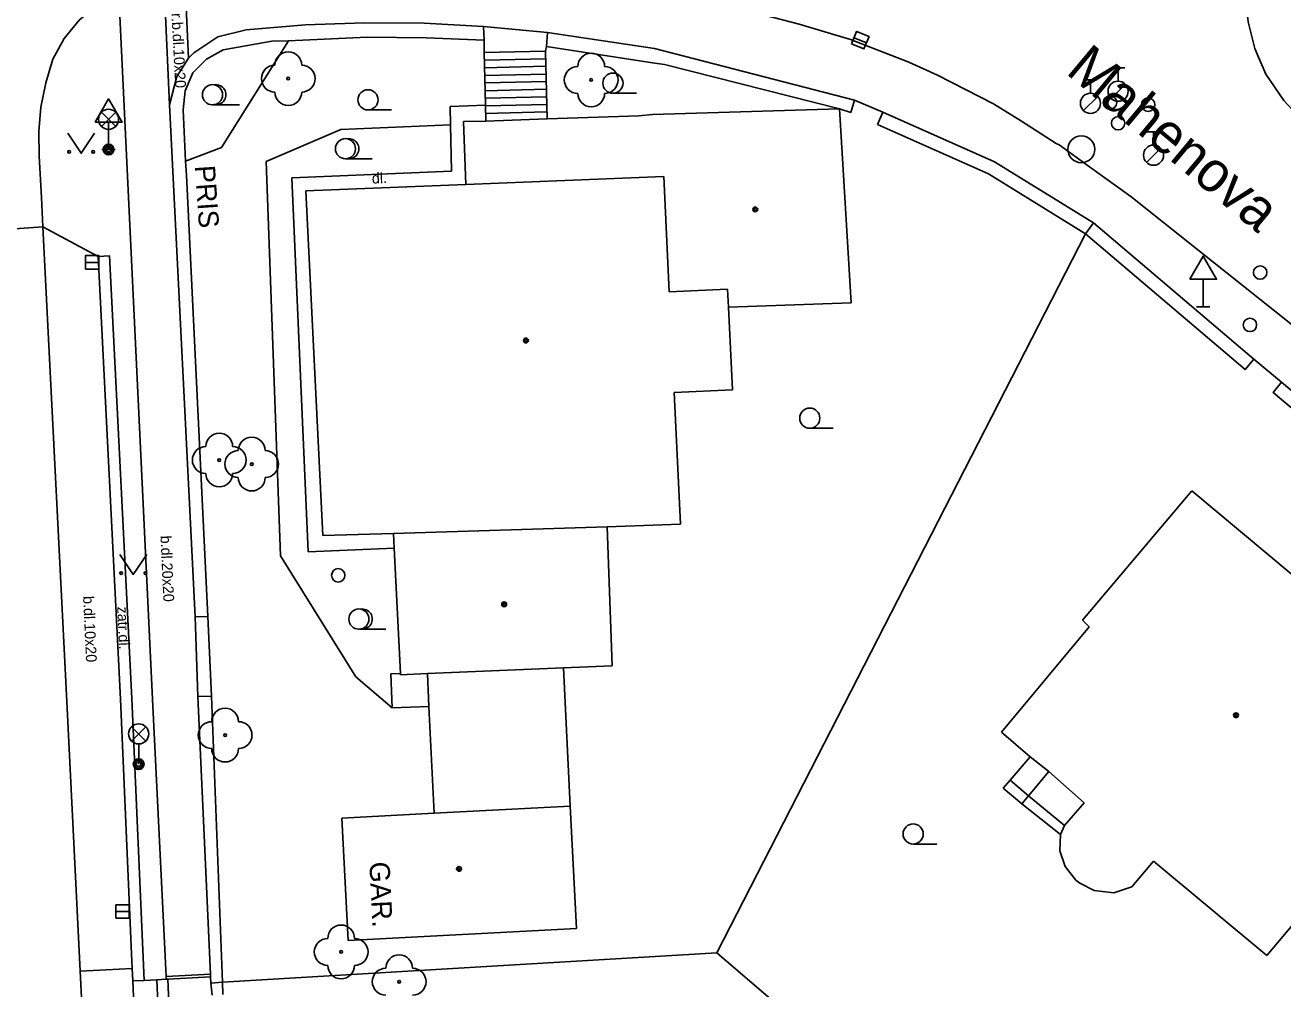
# Model space of a CAD drawing. Extents: x -600309 to -598967, y -1161267 to -1160292.
# Drawn here: x -599774.56 to -599727.72, y -1160467.69 to -1160431.81 of the extents above; entities that cross this region are included whole.
import ezdxf

# ---------------------------------------------------------------- set-up
doc = ezdxf.new("R2010")
doc.units = 0
for name, color, linetype in [('Level 10', 7, 'Continuous'), ('Level 11', 7, 'Continuous'), ('Level 21', 7, 'Continuous'), ('Level 22', 7, 'Continuous'), ('Level 27', 7, 'Continuous'), ('Level 28', 7, 'Continuous'), ('Level 33', 7, 'Continuous'), ('Level 34', 7, 'Continuous'), ('Level 36', 7, 'Continuous'), ('Level 39', 7, 'Continuous'), ('Level 40', 7, 'Continuous'), ('Level 41', 7, 'Continuous'), ('Level 5', 7, 'Continuous'), ('Level 50', 7, 'Continuous'), ('Level 51', 7, 'Continuous'), ('Level 7', 7, 'Continuous'), ('Level 8', 7, 'Continuous')]:
    doc.layers.add(name, color=color, linetype=linetype)

msp = doc.modelspace()

# ---------------------------------------------------------------- linework, layer by layer
at = {"layer": 'Level 10'}
for points in [[(-599725.57, -1160436.55), (-599726.98, -1160435.38), (-599727.23, -1160435.11), (-599727.69, -1160434.62), (-599728.36, -1160433.63), (-599728.67, -1160432.92), (-599728.67, -1160432.91), (-599728.77, -1160432.68), (-599729.02, -1160431.68), (-599729.04, -1160431.47), (-599729.12, -1160430.52), (-599729.02, -1160429.48), (-599728.93, -1160428.95), (-599727.47, -1160425.98), (-599727.28, -1160425.59)], [(-599773.52, -1160433.08), (-599773.1, -1160432.31), (-599772.54, -1160431.63), (-599771.87, -1160431.07), (-599771.1, -1160430.64)], [(-599750.81, -1160430.69), (-599747.65, -1160431.28), (-599745.73, -1160431.77), (-599743.83, -1160432.34), (-599741.65, -1160433.19), (-599740.59, -1160433.67), (-599738.5, -1160434.74)], [(-599774.03, -1160436.69), (-599774.05, -1160435.77), (-599773.97, -1160434.86), (-599773.79, -1160433.96), (-599773.52, -1160433.08)], [(-599738.5, -1160434.74), (-599737.46, -1160435.38), (-599736.16, -1160436.21), (-599736.06, -1160436.27), (-599734.93, -1160437.08), (-599733.39, -1160438.19)], [(-599773.9, -1160439.32), (-599773.95, -1160438.22), (-599774.03, -1160436.69)], [(-599733.39, -1160438.19), (-599726.76, -1160443.46)], [(-599773.9, -1160439.32), (-599771.84, -1160440.42)], [(-599771.84, -1160440.42), (-599771.01, -1160456.9), (-599770.6, -1160466.38), (-599770.57, -1160466.93)], [(-599770.57, -1160466.93), (-599770.55, -1160467.39), (-599770.4, -1160470.87), (-599770.38, -1160471.38)]]:
    msp.add_lwpolyline(points, dxfattribs=at)
at = {"layer": 'Level 11'}
for points in [[(-599771.1, -1160430.64), (-599771.04, -1160431.2), (-599769.82, -1160456.9)], [(-599769.18, -1160434.77), (-599769.34, -1160431.18), (-599768.56, -1160431.14), (-599768.47, -1160433.04)], [(-599757.4699, -1160432.37), (-599757.49, -1160431.86)], [(-599757.4699, -1160432.37), (-599757.46, -1160432.83)], [(-599755.15, -1160432.6), (-599755.11, -1160432.08)], [(-599757.46, -1160432.83), (-599755.18, -1160432.78)], [(-599757.46, -1160432.83), (-599757.41, -1160434.79), (-599757.4, -1160435.38)], [(-599755.18, -1160432.78), (-599755.15, -1160432.6)], [(-599755.18, -1160432.78), (-599755.12, -1160435.3)], [(-599757.45, -1160433.11), (-599755.17, -1160433.06)], [(-599757.45, -1160433.4), (-599755.17, -1160433.34)], [(-599757.44, -1160433.68), (-599755.1599, -1160433.63)], [(-599757.43, -1160433.96), (-599755.15, -1160433.9099)], [(-599757.43, -1160434.25), (-599755.15, -1160434.19)], [(-599758.73, -1160434.84), (-599757.41, -1160434.79)], [(-599757.42, -1160434.53), (-599755.14, -1160434.48)], [(-599757.4099, -1160434.81), (-599755.13, -1160434.76)], [(-599758.73, -1160434.84), (-599758.72, -1160435.52), (-599758.68, -1160437.24)], [(-599757.4099, -1160435.1), (-599755.13, -1160435.04)], [(-599764.63, -1160437.49), (-599758.68, -1160437.24)], [(-599764.63, -1160437.49), (-599764.02, -1160451.42)], [(-599773.9, -1160439.32), (-599776.88, -1160439.53), (-599779.91, -1160439.74)], [(-599772.51, -1160467.03), (-599773, -1160456.99), (-599773.9, -1160439.32)], [(-599771.84, -1160440.42), (-599771.41, -1160440.4), (-599770.58, -1160456.88), (-599770.13, -1160467.37)], [(-599760.81, -1160451.28), (-599764.02, -1160451.42)], [(-599754.26, -1160460.89), (-599754.51, -1160455.74)], [(-599760.58, -1160455.95), (-599760.94, -1160455.96)], [(-599760.89, -1160457.22), (-599760.94, -1160455.96)], [(-599759.58, -1160455.95), (-599759.52, -1160457.17), (-599759.33, -1160461.15)], [(-599769.82, -1160456.9), (-599769.31, -1160467.23), (-599769.31, -1160467.33)], [(-599759.52, -1160457.17), (-599760.89, -1160457.22)], [(-599737.88, -1160459.92), (-599737.14, -1160459.05)], [(-599736.44, -1160459.6), (-599737.19, -1160460.5)], [(-599738.14, -1160460.2199), (-599737.88, -1160459.92)], [(-599737.19, -1160460.5), (-599737.88, -1160459.92)], [(-599737.44, -1160460.8), (-599738.14, -1160460.2199)], [(-599737.19, -1160460.5), (-599737.44, -1160460.8)], [(-599735.86, -1160461.61), (-599737.19, -1160460.5)], [(-599736.01, -1160461.94), (-599737.44, -1160460.8)], [(-599772.51, -1160467.03), (-599770.57, -1160466.93)], [(-599772.29, -1160471.47), (-599772.51, -1160467.03)], [(-599769.31, -1160467.23), (-599767.66, -1160467.14)], [(-599770.13, -1160467.37), (-599770.55, -1160467.39)], [(-599769.31, -1160467.33), (-599769.65, -1160467.35), (-599770.13, -1160467.37)], [(-599769.65, -1160467.35), (-599769.5, -1160470.83)], [(-599769.31, -1160467.33), (-599769.25, -1160467.33), (-599767.65, -1160467.24)], [(-599769.25, -1160467.33), (-599769.1, -1160470.81)]]:
    msp.add_lwpolyline(points, dxfattribs=at)
at = {"layer": 'Level 21'}
for points in [[(-599767.25, -1160436.37), (-599764.75, -1160432.39)], [(-599762.8, -1160435.7), (-599765.58, -1160436.88)], [(-599762.8, -1160435.7), (-599758.72, -1160435.52)], [(-599767.25, -1160436.37), (-599768.58, -1160436.87)], [(-599765.58, -1160436.88), (-599765.05, -1160451.56)], [(-599765.05, -1160451.56), (-599762.24, -1160456.07)], [(-599762.24, -1160456.07), (-599760.89, -1160457.22)]]:
    msp.add_lwpolyline(points, dxfattribs=at)
at = {"layer": 'Level 22'}
for centre in [(-599764.76, -1160433.8), (-599753.48, -1160433.85), (-599767.33, -1160448), (-599766.12, -1160448.15), (-599767.11, -1160458.24), (-599762.79, -1160466.31), (-599760.63, -1160467.42)]:
    msp.add_circle(centre, 0.05, dxfattribs=at)
for centre, start, end in [((-599764.76, -1160433.3), 0, 180), ((-599753.48, -1160433.35), 0, 180), ((-599765.26, -1160433.8), 90, 270), ((-599764.26, -1160433.8), 270, 90), ((-599753.98, -1160433.85), 90, 270), ((-599752.98, -1160433.85), 270, 90), ((-599764.76, -1160434.3), 180, 0), ((-599753.48, -1160434.35), 180, 0), ((-599767.33, -1160447.5), 0, 180), ((-599766.12, -1160447.65), 0, 180), ((-599767.83, -1160448), 90, 270), ((-599766.62, -1160448.15), 90, 270), ((-599766.83, -1160448), 270, 90), ((-599765.62, -1160448.15), 270, 90), ((-599767.33, -1160448.5), 180, 0), ((-599766.12, -1160448.65), 180, 0), ((-599767.11, -1160457.74), 0, 180), ((-599767.61, -1160458.24), 90, 270), ((-599766.61, -1160458.24), 270, 90), ((-599767.11, -1160458.74), 180, 0), ((-599762.79, -1160465.81), 0, 180), ((-599763.29, -1160466.31), 90, 270), ((-599762.29, -1160466.31), 270, 90), ((-599760.63, -1160466.92), 0, 180), ((-599762.79, -1160466.81), 180, 0), ((-599761.13, -1160467.42), 90, 270), ((-599760.13, -1160467.42), 270, 90)]:
    msp.add_arc(centre, 0.5, start, end, dxfattribs=at)
at = {"layer": 'Level 27'}
for p, q in [((-599743.6915, -1160432.2756), (-599743.2285, -1160432.4644)), ((-599772.31, -1160440.64), (-599771.81, -1160440.64)), ((-599771.18, -1160464.81), (-599770.68, -1160464.81))]:
    msp.add_line(p, q, dxfattribs=at)
for points in [[(-599743.7859, -1160432.5071), (-599743.3229, -1160432.6959), (-599743.1341, -1160432.2329), (-599743.5971, -1160432.0441)], [(-599772.31, -1160440.89), (-599771.81, -1160440.89), (-599771.81, -1160440.39), (-599772.31, -1160440.39)], [(-599771.18, -1160465.06), (-599770.68, -1160465.06), (-599770.68, -1160464.56), (-599771.18, -1160464.56)]]:
    msp.add_lwpolyline(points, close=True, dxfattribs=at)
msp.add_circle((-599735.23, -1160436.43), 0.5, dxfattribs=at)
at = {"layer": 'Level 28'}
for p, q in [((-599734.11, -1160433.395), (-599733.61, -1160433.395)), ((-599733.86, -1160433.895), (-599733.86, -1160433.395)), ((-599735.14, -1160433.8449), (-599734.64, -1160433.8449)), ((-599734.89, -1160434.3449), (-599734.89, -1160433.8449)), ((-599734.118, -1160434.542), (-599733.588, -1160434.012)), ((-599735.148, -1160434.9919), (-599734.618, -1160434.4619)), ((-599732.79, -1160435.775), (-599732.29, -1160435.775)), ((-599732.54, -1160436.275), (-599732.54, -1160435.775)), ((-599732.798, -1160436.922), (-599732.268, -1160436.392))]:
    msp.add_line(p, q, dxfattribs=at)
for centre, radius in [((-599733.86, -1160434.27), 0.375), ((-599734.89, -1160434.7199), 0.375), ((-599734.1599, -1160434.69), 0.25), ((-599732.74, -1160434.77), 0.25), ((-599733.86, -1160435.46), 0.25), ((-599732.54, -1160436.65), 0.375), ((-599728.57, -1160441.02), 0.25), ((-599728.95, -1160442.9699), 0.25), ((-599762.9, -1160452.29), 0.25)]:
    msp.add_circle(centre, radius, dxfattribs=at)
at = {"layer": 'Level 33'}
for p, q in [((-599771.715, -1160435.58), (-599771.185, -1160435.05)), ((-599771.715, -1160435.05), (-599771.185, -1160435.58)), ((-599771.45, -1160435.69), (-599771.45, -1160436.44)), ((-599770.595, -1160458.46), (-599770.065, -1160457.93)), ((-599770.595, -1160457.93), (-599770.065, -1160458.46)), ((-599770.33, -1160458.57), (-599770.33, -1160459.32))]:
    msp.add_line(p, q, dxfattribs=at)
for centre, radius in [((-599771.45, -1160435.315), 0.375), ((-599771.45, -1160436.44), 0.2), ((-599771.45, -1160436.44), 0.1445), ((-599771.45, -1160436.44), 0.0876), ((-599770.33, -1160458.195), 0.375), ((-599770.33, -1160459.32), 0.2), ((-599770.33, -1160459.32), 0.1445), ((-599770.33, -1160459.32), 0.0876)]:
    msp.add_circle(centre, radius, dxfattribs=at)
at = {"layer": 'Level 34'}
for p, q in [((-599771.45, -1160435.422), (-599771.45, -1160436.44)), ((-599771.7, -1160436.44), (-599771.2, -1160436.44)), ((-599730.69, -1160441.272), (-599730.69, -1160442.29)), ((-599730.94, -1160442.29), (-599730.44, -1160442.29))]:
    msp.add_line(p, q, dxfattribs=at)
for points in [[(-599771.95, -1160435.422), (-599770.95, -1160435.422), (-599771.45, -1160434.556)], [(-599731.19, -1160441.272), (-599730.19, -1160441.272), (-599730.69, -1160440.406)]]:
    msp.add_lwpolyline(points, close=True, dxfattribs=at)
at = {"layer": 'Level 36'}
for p, q in [((-599752.67, -1160434.3449), (-599751.795, -1160434.3449)), ((-599767.58, -1160434.775), (-599766.58, -1160434.775)), ((-599761.79, -1160434.965), (-599760.915, -1160434.965)), ((-599762.63, -1160436.785), (-599761.63, -1160436.785)), ((-599745.34, -1160446.815), (-599744.465, -1160446.815)), ((-599762.13, -1160454.295), (-599761.13, -1160454.295)), ((-599741.49, -1160462.295), (-599740.615, -1160462.295))]:
    msp.add_line(p, q, dxfattribs=at)
for points in [[(-599772.97, -1160435.83), (-599772.47, -1160436.58), (-599771.97, -1160435.83)], [(-599771.03, -1160451.51), (-599770.53, -1160452.26), (-599770.03, -1160451.51)]]:
    msp.add_lwpolyline(points, dxfattribs=at)
for centre, radius in [((-599752.6701, -1160433.9698), 0.375), ((-599767.58, -1160434.3996), 0.375), ((-599761.7901, -1160434.5899), 0.375), ((-599762.63, -1160436.4096), 0.375), ((-599772.9202, -1160436.5298), 0.05), ((-599772.0208, -1160436.5298), 0.05), ((-599745.3401, -1160446.4399), 0.375), ((-599770.9802, -1160452.2098), 0.05), ((-599770.0808, -1160452.2098), 0.05), ((-599762.13, -1160453.9196), 0.375), ((-599741.4901, -1160461.9199), 0.375)]:
    msp.add_circle(centre, radius, dxfattribs=at)
for centre in [(-599767.455, -1160434.3996), (-599762.505, -1160436.4096), (-599762.005, -1160453.9196)]:
    msp.add_arc(centre, 0.375, 260.40593, 99.59407, dxfattribs=at)
at = {"layer": 'Level 39'}
for centre, radius in [((-599747.37, -1160438.67), 0.09), ((-599747.37, -1160438.67), 0.0398), ((-599755.9099, -1160443.55), 0.09), ((-599755.9099, -1160443.55), 0.0398), ((-599756.7199, -1160453.37), 0.09), ((-599756.7199, -1160453.37), 0.0398), ((-599729.4699, -1160457.5), 0.09), ((-599729.4699, -1160457.5), 0.0398), ((-599758.4, -1160463.2199), 0.09), ((-599758.4, -1160463.2199), 0.0398)]:
    msp.add_circle(centre, radius, dxfattribs=at)
at = {"layer": 'Level 5'}
for points in [[(-599757.4, -1160435.38), (-599755.12, -1160435.3)], [(-599755.12, -1160435.3), (-599751.7, -1160435.18)], [(-599751.7, -1160435.18), (-599751.2, -1160435.14)], [(-599751.2, -1160435.14), (-599744.23, -1160434.93)], [(-599744.23, -1160434.93), (-599743.8, -1160442.15)], [(-599758.24, -1160435.4), (-599757.4, -1160435.38)], [(-599758.15, -1160437.74), (-599758.24, -1160435.4)], [(-599758.15, -1160437.74), (-599750.78, -1160437.44)], [(-599750.78, -1160437.44), (-599750.58, -1160441.74)], [(-599764.1, -1160437.98), (-599758.15, -1160437.74)], [(-599763.4699, -1160450.81), (-599764.1, -1160437.98)], [(-599750.58, -1160441.74), (-599748.4, -1160441.64)], [(-599748.4, -1160441.64), (-599748.37, -1160442.31)], [(-599743.8, -1160442.15), (-599748.37, -1160442.31)], [(-599748.37, -1160442.31), (-599748.2199, -1160445.39)], [(-599748.2199, -1160445.39), (-599750.39, -1160445.49)], [(-599750.39, -1160445.49), (-599750.1599, -1160450.39)], [(-599735.19, -1160453.96), (-599731.12, -1160449.14)], [(-599731.12, -1160449.14), (-599720.92, -1160457.6599)], [(-599760.84, -1160450.73), (-599763.4699, -1160450.81)], [(-599752.89, -1160450.49), (-599760.84, -1160450.73)], [(-599760.58, -1160455.99), (-599760.58, -1160455.95), (-599760.81, -1160451.28), (-599760.84, -1160450.73)], [(-599750.1599, -1160450.39), (-599752.89, -1160450.49)], [(-599752.89, -1160450.49), (-599752.7, -1160455.6599)], [(-599734.94, -1160454.21), (-599735.19, -1160453.96)], [(-599738.2, -1160458.13), (-599734.94, -1160454.21)], [(-599752.7, -1160455.66), (-599754.51, -1160455.74), (-599759.58, -1160455.95), (-599760.58, -1160455.99)], [(-599720.92, -1160457.6599), (-599728.32, -1160466.44)], [(-599737.14, -1160459.05), (-599738.2, -1160458.13)], [(-599736.44, -1160459.6), (-599737.14, -1160459.05)], [(-599735.12, -1160460.76), (-599736.44, -1160459.6)], [(-599762.76, -1160461.33), (-599759.33, -1160461.15), (-599754.26, -1160460.89)], [(-599754.26, -1160460.89), (-599754.03, -1160465.44)], [(-599735.86, -1160461.61), (-599735.12, -1160460.76)], [(-599762.53, -1160465.88), (-599762.76, -1160461.33)], [(-599736.03, -1160462.55), (-599736.01, -1160461.94)], [(-599736.01, -1160461.94), (-599735.86, -1160461.61)], [(-599735.83, -1160463.13), (-599736.03, -1160462.55)], [(-599732.54, -1160462.93), (-599733.35, -1160463.89)], [(-599728.32, -1160466.44), (-599732.54, -1160462.93)], [(-599735.43, -1160463.64), (-599735.83, -1160463.13)], [(-599735.29, -1160463.75), (-599735.43, -1160463.64)], [(-599734.75, -1160464.02), (-599735.29, -1160463.75)], [(-599734.02, -1160464.11), (-599734.75, -1160464.02)], [(-599733.35, -1160463.89), (-599734.02, -1160464.11)], [(-599754.03, -1160465.44), (-599762.53, -1160465.88)]]:
    msp.add_lwpolyline(points, dxfattribs=at)
at = {"layer": 'Level 51'}
msp.add_lwpolyline([(-599732.93, -1160479.96), (-599748.8, -1160466.35)], dxfattribs=at)
at = {"layer": 'Level 7'}
for points in [[(-599769.18, -1160434.77), (-599768.91, -1160433.72), (-599768.47, -1160433.04), (-599768.28, -1160432.84), (-599767.38, -1160432.24), (-599766.33, -1160431.99)], [(-599766.33, -1160431.99), (-599764.12, -1160431.8), (-599763.03, -1160431.76), (-599761.91, -1160431.72), (-599759.7, -1160431.74), (-599757.49, -1160431.86)], [(-599768.31, -1160433.59), (-599767.81, -1160433.07), (-599767.18, -1160432.73), (-599765.37, -1160432.4), (-599764.75, -1160432.39), (-599761.82, -1160432.26), (-599759.63, -1160432.28), (-599757.4699, -1160432.37)], [(-599751.12, -1160432.68), (-599755.11, -1160432.08)], [(-599755.15, -1160432.6), (-599751.2, -1160433.21)], [(-599743.67, -1160434.6), (-599751.12, -1160432.68)], [(-599751.2, -1160433.21), (-599750.75, -1160433.28), (-599744.23, -1160434.93)], [(-599768.55, -1160437.4), (-599768.58, -1160436.87), (-599768.67, -1160434.96), (-599768.6, -1160434.25), (-599768.31, -1160433.59)], [(-599769.18, -1160434.77), (-599768.23, -1160453.84)], [(-599743.81, -1160435.06), (-599743.67, -1160434.6)], [(-599744.23, -1160434.93), (-599743.81, -1160435.06)], [(-599742.62, -1160435.05), (-599742.82, -1160435.51)], [(-599734.78, -1160439.17), (-599738.46, -1160436.9), (-599742.62, -1160435.05)], [(-599742.82, -1160435.51), (-599738.69, -1160437.34), (-599735.07, -1160439.58)], [(-599767.76, -1160453.82), (-599768.55, -1160437.4)], [(-599735.07, -1160439.58), (-599734.78, -1160439.17)], [(-599728.81, -1160444.25), (-599734.78, -1160439.17)], [(-599748.8, -1160466.35), (-599735.07, -1160439.58)], [(-599735.07, -1160439.58), (-599729.13, -1160444.63), (-599728.81, -1160444.25)], [(-599727.77, -1160445.1), (-599728.09, -1160445.48), (-599713.99, -1160457.33)], [(-599713.67, -1160456.95), (-599727.77, -1160445.1)], [(-599768.23, -1160453.84), (-599767.76, -1160453.82)], [(-599767.64, -1160467.47), (-599767.65, -1160467.24), (-599767.66, -1160467.14), (-599768.13, -1160456.8), (-599768.23, -1160453.84)], [(-599767.62, -1160456.79), (-599767.76, -1160453.82)], [(-599768.13, -1160456.8), (-599767.62, -1160456.79)], [(-599767.21, -1160467.44), (-599767.62, -1160456.79)], [(-599748.8, -1160466.35), (-599767.21, -1160467.44)], [(-599767.21, -1160467.44), (-599767.64, -1160467.47)], [(-599767.64, -1160467.47), (-599767.59, -1160467.92)], [(-599767.19, -1160467.9), (-599767.21, -1160467.44)]]:
    msp.add_lwpolyline(points, dxfattribs=at)
at = {"layer": 'Level 8'}
for points in [[(-599757.49, -1160431.86), (-599755.11, -1160432.08)], [(-599742.62, -1160435.05), (-599743.67, -1160434.6)], [(-599727.77, -1160445.1), (-599728.81, -1160444.25)]]:
    msp.add_lwpolyline(points, dxfattribs=at)

# ---------------------------------------------------------------- texts
at = {"layer": 'Level 40'}
for s, height, rotation, p in [('r.b.dl.10x20', 0.39993, 273, (-599769.11, -1160431.37)), ('dl.', 0.4, 2.45587, (-599761.64, -1160437.71)), ('b.dl.20x20', 0.4, 272.66055, (-599769.52, -1160450.82)), ('b.dl.10x20', 0.4, 272.66055, (-599772.4, -1160453.07)), ('zatr.dl.', 0.4, 272.66055, (-599771.13, -1160453.46))]:
    msp.add_text(s, height=height, rotation=rotation, dxfattribs=at).set_placement(p)
at = {"layer": 'Level 41'}
for s, rotation, p in [('PRIS', 273.93464, (-599768.24, -1160437.05)), ('GAR.', 272.84819, (-599761.74, -1160462.97))]:
    msp.add_text(s, height=0.75, rotation=rotation, dxfattribs=at).set_placement(p)
at = {"layer": 'Level 50'}
msp.add_text('Mahenova', height=1.5, rotation=320.24266, dxfattribs=at).set_placement((-599735.8473, -1160433.5864))

doc.saveas('drawing.dxf')
